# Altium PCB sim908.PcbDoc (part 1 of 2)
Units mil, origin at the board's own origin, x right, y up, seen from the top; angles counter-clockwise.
Board outline 6000 x 4000 mil, 2 copper layers (Top Layer, Bottom Layer); 77 components, 69 nets, 376 pads, 43 vias.
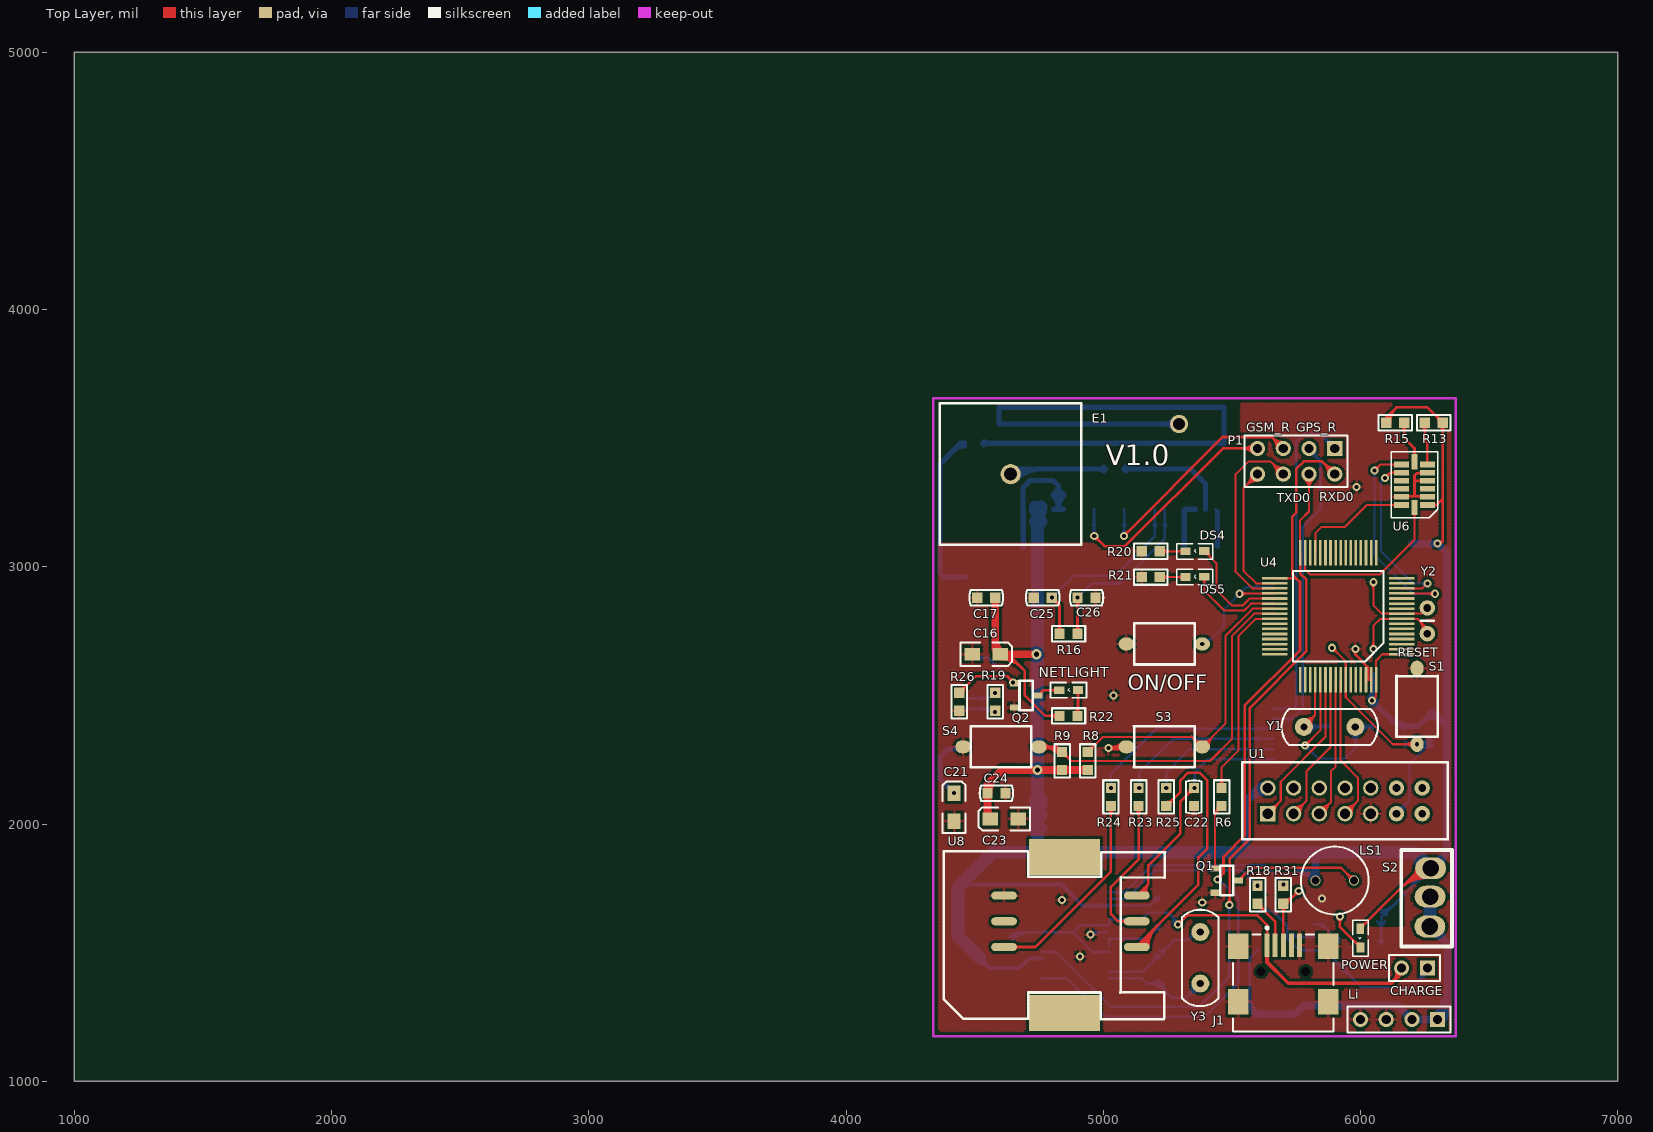
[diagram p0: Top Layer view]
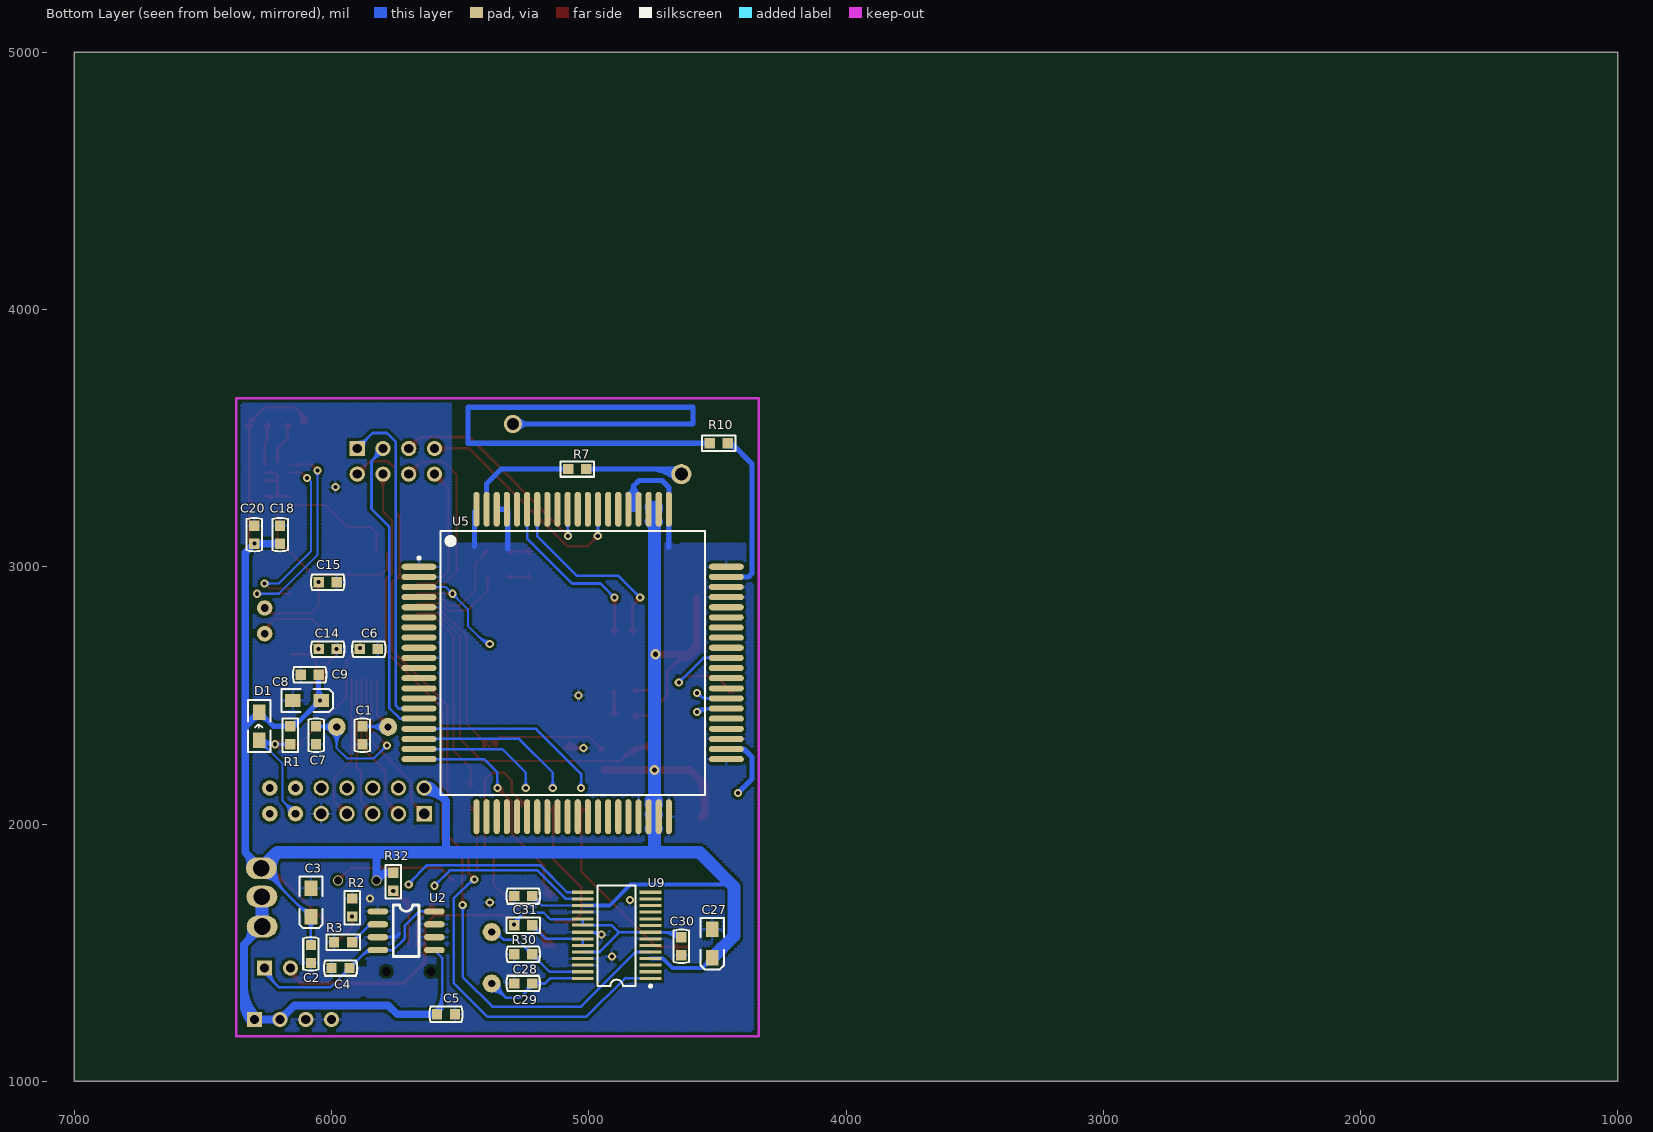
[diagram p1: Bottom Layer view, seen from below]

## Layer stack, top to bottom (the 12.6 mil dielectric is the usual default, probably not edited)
Top Layer: signal copper 1.4
Dielectric: dielectric 12.6, FR-4, Dk 4.8
Bottom Layer: signal copper 1.4

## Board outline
1000,1000 7000,1000 7000,5000 1000,5000

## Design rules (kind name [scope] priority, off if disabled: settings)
Clearance [All] p1: gap=10
HoleToHoleClearance [All] p1: gap=0 allowstackedmicrovias=TRUE
MinimumSolderMaskSliver [All] p1: minsoldermaskwidth=0
PolygonConnect [All] p1: connectstyle=Relief reliefconductorwidth=10 reliefentries=4 polygonreliefangle="90 Angle"
RoutingVias [All] p1: holewidth=28 width=50 viastyle="Through Hole" minholewidth=28 minwidth=50 maxholewidth=28 maxwidth=50
SilkToSilkClearance [All] p1: silktosilkclearance=0
SilkscreenOverComponentPads [All] p1: minsilkscreentomaskgap=0
SolderMaskExpansion [All] p1: expansion=4
TestPointUsage FabricationTestPointUsage [All] p1: valid=0 allowmultiple=FALSE
Testpoint FabricationTestpoint [All] p1: side=3 testpointundercomponent=TRUE minsize=40 maxsize=100 preferedsize=60 minholesize=0 maxholesize=40 preferedholesize=32 testpointgrid=1 style=297 order=0-112345678
Width [All] p1: maxlimit=100 minlimit=1 preferedwidth=10
20 further rules are at their usual default settings.

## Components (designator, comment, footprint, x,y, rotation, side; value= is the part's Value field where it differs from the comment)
C1 "Cap" C0603 5880,2310 r90 bottom
C2 "Cap" C0603 6080,1460 r90 bottom
C3 "Cap2" 3216C 6080,1640 r270 bottom
C4 "Cap" C0603 6000,1440 r180 bottom
C5 "Cap" C0603 5520,1260 r0 bottom
C6 "104" C0603 5820,2680 r0 bottom
C7 "Cap" C0603 6060,2310 r90 bottom
C8 "Cap2" 3216C 6040,2480 r180 bottom
C9 "Cap" C0603 6120,2580 r180 bottom
C14 "Cap" C0603 5980,2680 r0 bottom
C15 "Cap" C0603 5980,2940 r0 bottom
C16 "Cap2" 3216C 4600,2660 r0 top
C17 "Cap" C0603 4580,2880 r180 top
C18 "Cap" C0603 6200,3090 r90 bottom
C20 "Cap" C0603 6300,3160 r270 bottom
C21 "Cap2" 3216C 4420,2120 r90 top
C22 "Cap" C0603 5352.5,2070 r90 top
C23 "Cap2" 3216C 4560,2020 r180 top
C24 "Cap" C0603 4620,2120 r180 top
C25 "Cap" C0603 4800,2880 r180 top
C26 "Cap" C0603 4900,2880 r0 top
C27 "Cap2" 3216C 4520,1480 r270 bottom
C28 "Cap" C0603 5220,1493.33 r0 bottom
C29 "Cap" C0603 5220,1380 r0 bottom
C30 "Cap" C0603 4640,1560 r270 bottom
C31 "Cap" C0603 5220,1720 r0 bottom
CHARGE "充电" HDR1X2 6260,1440 r180 top (schematic designator Li)
D1 "1N4148" 1N5819 6280,2265.94 r270 bottom (schematic designator D401-1)
DS4 "LED" LED0603_AB 5360,3060 r180 top
DS5 "LED" LED0603_AB 5360,2960 r180 top
E1 "Antenna" GPS天线 4640,3360 r0 top
J1 "USB TYPE B" USB-Small 5700,1220 r270 top
Li "Comment" HDR1X4 6300,1240 r180 top
LS1 "Speaker" "BUZZER 7.6mm" 5900,1780 r0 top
NETLIGHT "LED" LED0603_AB 4869,2520 r180 top (schematic designator DS6)
ON/OFF "SW-PB" SWPB2-SMD 5080,2700 r0 top (schematic designator S5)
P1 "Header 4X2" HDR2X4 5900,3460 r180 top
POWER "LED" LED0603_AB 6000,1560 r270 top (schematic designator DS1)
Q1 "8050" NPN 5480,1780 r270 top
Q2 "" NPN 4700,2500 r270 top
R1 "Res2" R0603 6160,2310 r90 bottom
R2 "Res2" R0603 5920,1640 r90 bottom
R3 "Res2" R0603 5920,1540 r0 bottom
R6 "Res2" R0603 5460,2070 r90 top
R7 "Res2" R0603 5080,3380 r180 bottom
R8 "Res2" R0603 4940,2280 r270 top
R9 "Res2" R0603 4840,2280 r270 top
R10 "Res2" R0603 4460,3480 r0 bottom
R13 "Res2" R0603 6320,3560 r180 top
R15 "Res2" R0603 6100,3560 r0 top
R16 "Res2" R0603 4900,2740 r180 top
R18 "Res2" R0603 5600,1760 r270 top
R19 "Res2" R0603 4580,2440 r90 top
R20 "Res2" R0603 5220,3060 r180 top
R21 "Res2" R0603 5220,2960 r180 top
R22 "Res2" R0603 4900,2420 r180 top
R23 "Res2" R0603 5137.5,2140 r270 top
R24 "Res2" R0603 5030,2070 r90 top
R25 "Res2" R0603 5245,2140 r270 top
R26 "Res2" R0603 4440,2440 r90 top
R30 "Res2" R0603 5290,1606.67 r180 bottom
R31 "Res2" R0603 5700,1760 r270 top
R32 "Res2" R0603 5760,1740 r90 bottom
S1 "SW-PB" SWPB2-SMD 6220,2300 r90 top
S2 "5V" 小拨档开关 6260,1760 r90 top
S3 "SW-PB" SWPB2-SMD 5395,2300 r180 top
S4 "SW-PB" SWPB2-SMD 4760,2300 r180 top
U1 "MSP-JTAG" DIP14 5640,2040 r90 top
U2 "CN3052" SO-8 5820,1660 r180 bottom
U4 "MSP430F1612IPM" PM 6160,2660 r180 top
U5 "sim908" SIM908 5660,3000 r180 bottom
U6 "ADXL345" ADXL345_1 6260,3240 r180 top
U8 "SIM_CARD" SIM卡座 4380,1240 r0 top
U9 "PL2303" ssop28 4760,1400 r0 bottom
Y1 "8M" XTAL-0.2 5900,2220 r180 top
Y2 "32.768K" OSC1 6260,2840 r270 top
Y3 "12M" XTAL-0.2 5220,1460 r90 top

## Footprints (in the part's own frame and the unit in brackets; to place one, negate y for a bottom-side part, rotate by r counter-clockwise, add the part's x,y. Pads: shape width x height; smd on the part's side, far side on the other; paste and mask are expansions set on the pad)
1N5819 [mil]
  rect 60x50 smd: A(-60,-1) K(-169,-1)
  silkscreen extent -216,-44 -14,42
3216C [mil]
  rect 60x50 smd: 1(0,0) 2(-110,0)
  silkscreen extent -155,-45 45,45
ADXL345_1 [mm]
  rect 1.5x0.55 smd: 1(0,0) 2(0,-0.813) 3(0,-1.6) 4(0,-2.4) 5(0,-3.2) 6(0,-4) 8(2.553,-4) 9(2.553,-3.2) 10(2.553,-2.4) 11(2.553,-1.6) 12(2.553,-0.8) 13(2.553,0)
  rect 0.55x1.5 smd: 7(1.27,-4.267) 14(1.27,0.254)
  silkscreen extent -1.04,-5.26 3.57,1.26
"BUZZER 7.6mm" [mm]
  round 1 hole 0.762: 1(-1.9,0) 2(1.9,0)
  silkscreen extent -3.35,-3.35 3.35,3.35
C0603 [mil]
  rect 40x40 smd: 1(0,0) 2(70,0)
  silkscreen extent -30,-30 100,30
DIP14 [mil]
  rect 60x60 hole 40: 1(0,0)
  round 60 hole 40: 2(100,0) 3(0,-100) 4(100,-100) 5(0,-200) 6(100,-200) 7(0,-300) 8(100,-300) 9(0,-400) 10(100,-400)
  round 60 hole 30: 11(0,-500) 12(100,-500) 13(0,-600) 14(100,-600)
  silkscreen extent -100,-700 200,100
GPS天线 [mm]
  round 2 hole 1.3: 1(0,0)
  silkscreen extent -6.98,-6.98 6.98,6.98
HDR1X2 [mm] "Connector; Header; 2 Position"
  rect 1.5x1.5 hole 0.9: 1(0,0)
  round 1.5 hole 0.9: 2(2.54,0)
  silkscreen extent -1.27,-1.27 3.81,1.27
HDR1X4 [mm] "Connector; Header; 4 Position"
  rect 1.5x1.5 hole 0.9: 1(0,0)
  round 1.5 hole 0.9: 2(2.54,0) 3(5.08,0) 4(7.62,0)
  silkscreen extent -1.27,-1.27 8.89,1.27
HDR2X4 [mm] "Connector; Header; 4x2 Position"
  rect 1.5x1.5 hole 0.9: 1(0,0)
  round 1.5 hole 0.9: 2(0,2.54) 3(2.54,0) 4(2.54,2.54) 5(5.08,0) 6(5.08,2.54) 7(7.62,0) 8(7.62,2.54)
  silkscreen extent -1.27,-1.27 8.89,3.81
LED0603_AB [mil]
  rect 40x30 smd: 1(-32.93,-1) 2(40,0)
  silkscreen extent -66,-30 74,30
NPN [mm]
  rect 0.6x0.9 smd: 1(-1.2,-1.15) 2(1.2,-1.15) 3(0,1.15)
  silkscreen extent -1.45,-0.65 1.45,0.65
OSC1 [mil]
  round 60 hole 30: 1(0,0) 2(100,0)
  silkscreen extent 50,-25 50,25
PM [mm]
  rect 2.54x0.254 smd: 1(0,0) 2(0,-0.5) 3(0,-1) 4(0,-1.5) 5(0,-2) 6(0,-2.5) 7(0,-3) 8(0,-3.5) 9(0,-4) 10(0,-4.5) 11(0,-5) 12(0,-5.5) 13(0,-6) 14(0,-6.5) 15(0,-7) 16(0,-7.5) 33(12.54,-7.5) 34(12.54,-7) 35(12.54,-6.5) 36(12.54,-6) 37(12.54,-5.5) 38(12.54,-5) 39(12.54,-4.5) 40(12.54,-4) 41(12.54,-3.5) 42(12.54,-3) 43(12.54,-2.5) 44(12.54,-2) 45(12.54,-1.5) 46(12.54,-1) 47(12.54,-0.5) 48(12.54,0)
  rect 0.254x2.54 smd: 17(2.52,-10.02) 18(3.02,-10.02) 19(3.52,-10.02) 20(4.02,-10.02) 21(4.52,-10.02) 22(5.02,-10.02) 23(5.52,-10.02) 24(6.02,-10.02) 25(6.52,-10.02) 26(7.02,-10.02) 27(7.52,-10.02) 28(8.02,-10.02) 29(8.52,-10.02) 30(9.02,-10.02) 31(9.52,-10.02) 32(10.02,-10.02) 49(10.02,2.52) 50(9.52,2.52) 51(9.02,2.52) 52(8.52,2.52) 53(8.02,2.52) 54(7.52,2.52) 55(7.02,2.52) 56(6.52,2.52) 57(6.02,2.52) 58(5.52,2.52) 59(5.02,2.52) 60(4.52,2.52) 61(4.02,2.52) 62(3.52,2.52) 63(3.02,2.52) 64(2.52,2.52)
  silkscreen extent 1.81,-8.21 10.73,0.71
R0603 [mil]
  rect 40x40 smd: 1(0,0) 2(70,0)
  silkscreen extent -30,-30 100,30
SIM908 [mm] "QFP, 80-Leads, Body 33.0x33.0mm (max), Pitch 1.00mm, IPC Medium Density"
  oval 3.45x0.6 smd: 1(0,0) 2(0,-1) 3(0,-2) 4(0,-3) 5(0,-4) 6(0,-5) 7(0,-6) 8(0,-7) 9(0,-8) 10(0,-9) 11(0,-10) 12(0,-11) 13(0,-12) 14(0,-13) 15(0,-14) 16(0,-15) 17(0,-16) 18(0,-17) 19(0,-18) 20(0,-19) 41(30.35,-19) 42(30.35,-18) 43(30.35,-17) 44(30.35,-16) 45(30.35,-15) 46(30.35,-14) 47(30.35,-13) 48(30.35,-12) 49(30.35,-11) 50(30.35,-10) 51(30.35,-9) 52(30.35,-8) 53(30.35,-7) 54(30.35,-6) 55(30.35,-5) 56(30.35,-4) 57(30.35,-3) 58(30.35,-2) 59(30.35,-1) 60(30.35,0)
  oval 0.6x3.45 smd: 21(5.675,-24.675) 22(6.675,-24.675) 23(7.675,-24.675) 24(8.675,-24.675) 25(9.675,-24.675) 26(10.675,-24.675) 27(11.675,-24.675) 28(12.675,-24.675) 29(13.675,-24.675) 30(14.675,-24.675) 31(15.675,-24.675) 32(16.675,-24.675) 33(17.675,-24.675) 34(18.675,-24.675) 35(19.675,-24.675) 36(20.675,-24.675) 37(21.675,-24.675) 38(22.675,-24.675) 39(23.675,-24.675) 40(24.675,-24.675) 61(24.675,5.675) 62(23.675,5.675) 63(22.675,5.675) 64(21.675,5.675) 65(20.675,5.675) 66(19.675,5.675) 67(18.675,5.675) 68(17.675,5.675) 69(16.675,5.675) 70(15.675,5.675) 71(14.675,5.675) 72(13.675,5.675) 73(12.675,5.675) 74(11.675,5.675) 75(10.675,5.675) 76(9.675,5.675) 77(8.675,5.675) 78(7.675,5.675) 79(6.675,5.675) 80(5.675,5.675)
  silkscreen extent -0.13,-22.55 28.23,3.55
SIM卡座 [mm]
  oval 2.54x0.8 smd: 1(19.062,12.237) 2(19.062,9.697) 3(19.062,7.157) 4(5.954,12.237) 5(5.954,9.697) 6(5.954,7.157)
  rect 7x3.556 smd: ""(11.939,0.626) ""(11.941,16.052)
  silkscreen extent -0.01,0.01 21.85,16.61
SO-8 [mil]
  oval 80x24 smd: 1(0,0) 2(0,-50) 3(0,-100) 4(0,-150) 5(220,-150) 6(220,-100) 7(220,-50) 8(220,0)
  silkscreen extent 60,-175 160,25
ssop28 [mm]
  rect 2.15x0.305 smd: 1(0,0) 2(0,-0.65) 3(0,-1.3) 4(0,-1.95) 5(0,-2.6) 6(0,-3.25) 7(0,-3.9) 8(0,-4.55) 9(0,-5.2) 10(0,-5.85) 11(0,-6.552) 12(0,-7.202) 13(0,-7.852) 14(0,-8.502) 15(6.7,-8.502) 16(6.7,-7.852) 17(6.7,-7.202) 18(6.7,-6.552) 19(6.7,-5.85) 20(6.7,-5.252) 21(6.7,-4.55) 22(6.7,-3.9) 23(6.7,-3.25) 24(6.7,-2.6) 25(6.7,-1.95) 26(6.7,-1.3) 27(6.7,-0.65) 28(6.7,0)
  silkscreen extent -0.12,-9.14 5.22,0.9
SWPB2-SMD [mil]
  oval 60x50 smd: 1(10,0) 2(305,0)
  silkscreen extent 40,-80 276,80
USB-Small [mm] "Connector; USB2.0, Type B, SM; 5 Position; Right Angle"
  rect 2.3x0.5 smd: 1(-7.85,-1.6) 2(-7.85,-0.8) 3(-7.85,0) 4(-7.85,0.8) 5(-7.85,1.6)
  rect 2.5x2 smd: 6(-7.75,4.45) 7(-2.25,4.45) 8(-7.75,-4.45) 9(-2.25,-4.45)
  round 0.6 hole 0.9 unplated: MH1(-5.25,2.2) MH2(-5.25,-2.2)
  silkscreen extent -9.67,-4.95 0.7,4.95, body extent -8.9,-4.95 0.7,4.95, height 3.9
XTAL-0.2 [mil]
  round 70 hole 28: 1(-79.92,-157.48) 2(120.08,-157.48)
  silkscreen extent -168,-228 207,-86
小拨档开关 [mil]
  oval 85x120 hole 65: 1(-158.46,-9.84) 2(-42.32,-10.83) 3(67.91,-12.8)
  silkscreen extent -236,-96 139,101

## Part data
C1 C2 C3 C4 C5 C7 C8 C9 C14 C15 C16 C17 C18 C20 C21 C22 C23 C24 C25 C26 C27 C28 C29 C30 C31: "Capacitor"
C6: library part Cap, "Capacitor"
CHARGE: library part "Header 2", "Header, 2-Pin"
D1: library part DIODE1, "Diode"
DS4 DS5 NETLIGHT POWER: library part LED3, "Typical BLUE SiC LED"
J1: library part miniUSB, "USB, SMD, Type B, Molex"
LS1: "Loudspeaker"
ON/OFF S1 S3 S4: "Switch"
P1: "Header, 4-Pin, Dual row"
Q1: library part QNPN, "NPN Bipolar Transistor"
Q2: library part IRF540
R1 R2 R3 R6 R7 R8 R9 R10 R13 R15 R16 R18 R19 R20 R21 R22 R23 R24 R25 R26 R30 R31 R32: "Resistor"
S2: library part CON3, "Connector"
U4: "MSP430F1611IPM"
Y1 Y2 Y3: library part XTAL, "Crystal Oscillator"

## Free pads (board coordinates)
  round 70.87 hole 47.24: 1(5295,3555)

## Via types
v1: diameter 31.5, hole 15.75, Top Layer to Bottom Layer, 41 vias
v2: diameter 39.37, hole 19.68, Top Layer to Bottom Layer, 2 vias

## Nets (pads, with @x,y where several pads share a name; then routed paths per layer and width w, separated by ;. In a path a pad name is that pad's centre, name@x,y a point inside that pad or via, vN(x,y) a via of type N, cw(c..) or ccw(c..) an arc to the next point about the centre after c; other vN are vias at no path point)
3.3V: C2.2 C3.1 C8.1 C9.2 C16.1 C17.1 C18.1 C20.2 C23.1 C24.2 C27.1 C31.1 D1.K LS1.1 POWER.1 R1.2 R8.2 R9.2 R13.1 R15.1 R22.2 R32.2 S2.3 U1.2 U4.1 U4.64 U5.38 U5.39 U5.62 U5.63 U6.1 U9.4 U9.17 | length 13212.1
  Top Layer w8: v1(6045,2480) 6060.79,2495.79 U4.64@6060.79,2560.79 6060.79,2635.79 6085,2660 U4.1@6160,2660
  Top Layer w10: C16.1@4600,2660 4630,2660 4695,2595 4695,2499.54 4774.54,2420 R22.2@4830,2420 ; C16.1@4605,2640 cw(c4605,2531.36) 4681.82,2608.18 ; C16.1@4605,2650 cw(c4605,2565.5) 4664.75,2625.25 ; C16.1@4605,2660 cw(c4605,2599.64) 4647.68,2642.32 ; C16.1@4605,2670 cw(c4605,2633.79) 4630.61,2659.39 ; R22.2@4819.39,2409.39 ccw(c4793.79,2383.79) 4793.79,2420 ccw(c4793.79,2456.21) R22.2@4819.39,2430.61 ; POWER.1@5999,1592.93 6233.98,1827.91 S2.3@6272.8,1827.91 ; POWER.1@5999,1607.93 ccw(c5999,1644.14) 6024.61,1618.53 ; POWER.1@6009,1597.93 cw(c6021.07,1597.93) POWER.1@6012.54,1606.46 ; R15.1@6095,3560 cw(c6131.21,3560) 6105.61,3585.61 ; R15.1@6100,3560 6100,3580 6140,3620 6260,3620 R13.1@6320,3560 6320,3265 ; R15.1@6105,3560 cw(c6165.36,3560) 6122.68,3602.68 ; R15.1@6115,3560 cw(c6199.5,3560) 6139.75,3619.75 ; 6154.9,1748.83 cw(c6255.3,1648.43) S2.3@6255.3,1790.41 ; 6171.97,1765.9 cw(c6255.3,1682.58) S2.3@6255.3,1800.41 ; 6189.04,1782.97 cw(c6255.3,1716.72) S2.3@6255.3,1810.41 ; 6206.11,1800.04 cw(c6255.3,1750.86) S2.3@6255.3,1820.41 ; 6206.35,1800.27 ccw(c6178.71,1827.91) S2.3@6217.8,1827.91 ; U6.1@6260,3240 6295,3240 6320,3265 ; U6.1@6282.82,3235.88 cw(c6292.77,3225.93) 6292.77,3240 cw(c6292.77,3254.07) U6.1@6282.82,3244.12 ; v1@6305,3085 6320,3100 ; R13.1@6305,3560 ccw(c6268.79,3560) 6294.39,3585.61 ccw(c6320,3611.21) R13.1@6320,3575 ; v1@6306.17,3098.8 ccw(c6312.37,3107.63) 6320,3100 ; R13.1@6309.39,3549.39 cw(c6283.79,3523.79) 6320,3523.79 cw(c6356.21,3523.79) R13.1@6330.61,3549.39 ; 6320,3100 6320,3265
  Top Layer w30: C23.1@4550,2030 C24.2@4550,2120 4550,2155 4605,2210 v2(4745,2210) R9.2@4840,2210 R8.2@4940,2210 ; 4550,2056.21 ccw(c4591.21,2056.21) C23.1@4562.07,2027.07 ; C24.2@4555,2120 cw(c4651.57,2120) 4583.28,2188.28 ; 4580,2720.36 ccw(c4655.36,2720.36) C16.1@4602.07,2667.07 ; C17.1@4580,2880 4580,2680 C16.1@4600,2660 ; 4630,2660 v2(4740,2660)
  Bottom Layer w8: U9.17@5023.78,1683.54 5183.54,1683.54 C31.1@5220,1720 ; C31.1@5204,1720 cw(c5165.37,1720) 5192.69,1692.69 cw(c5220,1665.37) C31.1@5220,1704
  Bottom Layer w10: C3.1@6065.86,1620.86 cw(c6031.72,1586.72) 6080,1586.72 cw(c6128.28,1586.72) C3.1@6094.14,1620.86 ; C2.2@6071,1542 ccw(c6057.5,1560) 6080,1560 ; C2.2@6080,1530 6080,1560 ; C3.1@6080,1655 ccw(c6080,1703) 6113.94,1669.06 ; C3.1@6080,1665 ccw(c6080,1737.14) 6131.01,1686.13 ; C2.2@6089,1542 cw(c6102.5,1560) 6080,1560 ; C3.1@6100,1645 cw(c6124.43,1645) 6107.15,1662.27 ; 6178.9,1734.02 ccw(c6085.01,1827.91) S2.3@6217.8,1827.91 ; 6195.98,1751.09 ccw(c6119.16,1827.91) S2.3@6227.8,1827.91 ; 6213.05,1768.16 ccw(c6153.3,1827.91) S2.3@6237.8,1827.91 ; 6221.15,1776.27 cw(c6255.3,1742.13) S2.3@6255.3,1790.41 ; 6230.12,1785.24 ccw(c6187.44,1827.91) S2.3@6247.8,1827.91 ; S2.3@6272.8,1827.91 6084.88,1640 C3.1@6080,1640 6080,1560
  Bottom Layer w15: 4460,1765 4837.09,1765 4918.54,1683.54 U9.17@5023.78,1683.54 ; C27.1@4520,1457.5 cw(c4520,1403.18) 4558.41,1441.59 ; C27.1@4520,1480 4560,1440 4675,1440 4711.77,1476.77 U9.4@4760,1476.77 ; C27.1@4537.5,1475 ccw(c4567.68,1475) 4546.34,1453.66 ; 4705.91,1470.91 cw(c4723.68,1453.15) 4723.68,1478.27 ccw(c4723.68,1453.15) 4705.91,1470.91
  Bottom Layer w20: C8.1@6034.39,2490.61 ccw(c5996.72,2528.28) 6050,2528.28 ; C8.1@6040,2480 6050,2490 C9.2@6050,2580 ; C8.1@6040.94,2484.06 ccw(c6019.05,2505.95) 6050,2505.95 ; C9.2@6042.93,2572.93 cw(c6025.86,2555.86) 6050,2555.86 cw(c6074.14,2555.86) C9.2@6057.07,2572.93 ; C8.1@6045,2465 cw(c6045,2428.79) 6070.61,2454.39 cw(c6096.21,2480) C8.1@6060,2480 ; v1(6045,2480) 6145,2380 R1.2@6160,2380 6226.06,2380 D1.K@6281,2434.94 ; 6117.32,2407.68 ccw(c6160,2450.36) R1.2@6160,2390 ; R1.2@6167.07,2372.93 cw(c6184.14,2355.86) 6184.14,2380 cw(c6184.14,2404.14) R1.2@6167.07,2387.07 ; 6246.86,2400.79 cw(c6281,2366.65) D1.K@6281,2414.94 ; D1.K@6258.93,2412.87 ccw(c6241.86,2429.94) D1.K@6266,2429.94
  Bottom Layer w30: U5.62@4725.95,3220.91 ccw(c4745.2,3245.51) U5.63@4767.28,3223.43 ; U5.39@4727.91,2028.54 4745,2028.54 U5.38@4767.28,2028.54 ; U5.62@4727.91,3223.43 U5.63@4767.28,3223.43 4754.43,3210.57 ; 5554.64,2089.64 cw(c5640,2004.29) U1.2@5640,2125 ; 5555,1890 5555,2090 5605,2140 ; 5587.5,2122.5 cw(c5612.74,2097.26) U1.2@5631.93,2127.35 ; 5605.86,2140.86 cw(c5640,2106.71) U1.2@5640,2155 ; U1.2@5629.14,2129.66 ccw(c5605,2106.67) 5605,2140 ; U1.2@5629.14,2150.34 cw(c5605,2173.33) 5605,2140 ; U1.2@5640,2140 5605,2140 ; R32.2@5760,1810 5795.2,1810 LS1.1@5825.2,1780 5825.2,1889.8 ; C18.1@6200,3090 v1(6300,3090) 6335,3055 6335,2380.94 ; S2.3@6272.8,1827.91 6335,1890.12 ; D1.K@6281,2419.94 cw(c6281,2383.72) 6306.61,2409.33 ; D1.K@6281,2434.94 6335,2380.94 ; S2.3@6317.32,1832.98 cw(c6380.32,1844.8) 6335,1890.12 ; 6335,1890.12 6335,2380.94
  Bottom Layer w50: C27.1@4520,1480 4435,1565 4435,1755 4570,1890 4745,1890 ; U5.39@4737.24,1981.77 cw(c4718.5,1963.03) 4745,1963.03 ; U5.39@4737.24,2037.87 cw(c4718.5,2019.13) 4745,2019.13 ; U5.39@4737.24,2075.32 ccw(c4718.5,2094.06) 4745,2094.06 ; 4737.24,2093.97 cw(c4718.5,2075.24) 4745,2075.24 ; U5.62@4737.24,3176.65 cw(c4718.5,3157.91) 4745,3157.91 ; U5.62@4737.24,3232.75 cw(c4718.5,3214.02) 4745,3214.02 ; 4745,1950.48 cw(c4789.24,1950.48) U5.38@4757.96,1981.77 ; 4745,2006.59 cw(c4789.24,2006.59) U5.38@4757.96,2037.87 ; 4745,2062.69 cw(c4789.24,2062.69) 4757.96,2093.97 ; 4745,2106.6 ccw(c4789.24,2106.6) U5.38@4757.96,2075.32 ; 4745,3145.37 cw(c4789.24,3145.37) U5.63@4757.96,3176.65 ; 4745,3201.47 cw(c4789.24,3201.47) U5.63@4757.96,3232.75 ; 4754.43,3210.57 4745,3201.14 v2(4745,2210) 4745,2028.54 4745,1890 ; 6147.91,1890 6120,1890 ; 6213.05,1887.66 cw(c6153.3,1827.91) S2.3@6237.8,1827.91 ; S2.3@6272.8,1827.91 6210.71,1890 6120,1890 ; 4745,1890 5555,1890 6120,1890
5V: C30.1 CHARGE.2 J1.1 R30.1 U9.8 U9.19 U9.20 U9.24 | length 2468.5
  Top Layer w10: v1(5290,1610) 5325,1645 5600,1645 5637.01,1607.99 J1.1@5637.01,1529.06 ; v1@5290,1620.75 ccw(c5290,1646.7) 5308.35,1628.35 ccw(c5326.7,1610) v1@5300.75,1610 ; J1.1@5633.58,1567.91 ccw(c5625.32,1576.18) 5637.01,1576.18 ccw(c5648.7,1576.18) J1.1@5640.43,1567.91
  Top Layer w15: J1.1@5637.01,1529.06 5637.01,1462.99 5719.02,1380.98 6120.98,1380.98 CHARGE.2@6160,1420 ; 6130.99,1390.99 ccw(c6104.02,1417.95) CHARGE.2@6139.5,1431.93 ; 6147.17,1407.17 ccw(c6127.23,1427.1) CHARGE.2@6153.46,1437.43
  Bottom Layer w10: C30.1@4636.46,1563.54 cw(c4674.12,1525.88) 4674.12,1579.13 ; C30.1@4640,1560 4659.13,1579.13 U9.8@4760,1579.13 4760.87,1580 4880,1580 ; C30.1@4643.54,1556.46 cw(c4698.26,1501.74) 4698.26,1579.13 ; C30.1@4650.61,1549.39 cw(c4722.41,1477.59) U9.8@4722.41,1579.13 ; U9.24@5023.78,1502.36 4957.64,1502.36 4880,1580 ; 5254.97,1655.03 cw(c5206.6,1606.67) R30.1@5275,1606.67 ; 5264.58,1645.42 cw(c5229.16,1610) R30.1@5279.25,1610 ; 5272.04,1637.96 cw(c5240.74,1606.67) R30.1@5285,1606.67 ; 5281.65,1628.35 cw(c5263.3,1610) R30.1@5289.25,1610 ; R30.1@5290,1606.67 5290,1620 5255,1655 5175,1655 5150.31,1630.31 U9.19@5023.78,1630.31 U9.20@5023.78,1606.77 4911.77,1606.77 4885,1580 4880,1580
5V_LI: C4.2 CHARGE.1 U2.4 U2.8 | length 1234.2
  Top Layer w10: CHARGE.1@6260,1420 CHARGE.1@6260,1440
  Bottom Layer w10: U2.8@5600,1660 5660,1660 5715,1605 5715,1555 5760,1510 U2.4@5820,1510 5860,1510 C4.2@5930,1440 6005,1365 6205,1365 CHARGE.1@6260,1420 ; U2.8@5632.95,1655.05 cw(c5644.9,1643.1) 5644.9,1660 cw(c5644.9,1676.9) U2.8@5632.95,1664.95 ; U2.4@5787.05,1505.05 ccw(c5775.1,1493.1) 5775.1,1510 ccw(c5775.1,1526.9) U2.4@5787.05,1514.95 ; U2.4@5848,1503 cw(c5848,1457.13) 5880.44,1489.56 ; U2.4@5848,1513 cw(c5848,1491.27) 5863.36,1506.64 ; C4.2@5915,1440 ccw(c5878.79,1440) 5904.39,1465.61 ccw(c5930,1491.21) C4.2@5930,1455 ; C4.2@5930,1425 cw(c5930,1388.79) 5955.61,1414.39 cw(c5981.21,1440) C4.2@5945,1440 ; 6215,1375 ccw(c6163.36,1426.64) CHARGE.1@6235.7,1436.64 ; 6229.22,1389.22 ccw(c6188.35,1430.1) CHARGE.1@6245.61,1438.01 ; 6243.45,1403.45 ccw(c6213.34,1433.55) CHARGE.1@6255.52,1439.38
D+: R31.1 U9.15 | length 789.1
  Bottom Layer w10: U9.15@5023.78,1734.72 5084.72,1734.72 5190,1840 5230,1840 5628.28,1840 v1@5699.14,1769.14 ; 5679.33,1788.95 cw(c5655.38,1765) v1@5689.25,1765 ; 5687.26,1781.03 ccw(c5700,1793.77) v1@5700,1775.75
  other v1: 5700,1765
D-: R18.1 U9.16 | length 687.8
  Bottom Layer w10: U9.16@5023.78,1709.13 5089.13,1709.13 5200,1820 5540,1820 v1(5600,1760) ; v1@5589.25,1760 ccw(c5563.3,1760) 5581.65,1778.35 ccw(c5600,1796.7) v1@5600,1770.75
GND: C1.1 C2.1 C3.2 C4.1 C5.1 C6.1 C7.1 C8.2 C9.1 C14.1 C15.1 C16.2 C17.2 C18.2 C20.1 C21.2 C22.1 C23.2 C24.1 C25.2 C26.2 C27.2 C28.2 C29.2 C30.2 C31.2 J1.5 J1.6 J1.7 J1.8 J1.9 Li.3 Li.4 ON/OFF.1 Q1.2 Q2.2 R2.2 R3.2 R20.2 R21.2 R26.1 S1.2 S3.2 S4.2 U1.9 U2.1 U2.3 U2.6 U2.7 U4.62 U4.63 U5.1 U5.2 U5.5 U5.10 U5.14 U5.37 U5.40 U5.41 U5.43 U5.57 U5.58 U5.60 U5.61 U5.64 U5.65 U5.77 U5.78 U5.80 U6.2 U6.4 U6.5 U6.12 U8.4 U9.7 U9.18 U9.21 U9.25 U9.26 | length 2029.6
  Top Layer w10: v1@5973.63,2671.35 cw(c5964.34,2658.73) 5980,2658.73 ; v1(5980,2680) 5980,2658.73 ; v1@5986.37,2671.35 ccw(c5995.66,2658.73) 5980,2658.73 ; U4.62@6021.42,2560.79 6030,2560.79 ; U4.63@6041.1,2560.79 6030,2560.79 ; U6.12@6159.5,3271.5 6162.53,3274.53 6257.47,3274.53 U6.2@6254.83,3277.17 ; 6212.83,3277.17 6210,3280 6210,3325 ; 6221.13,3274.53 cw(c6221.13,3251.83) U6.2@6237.18,3267.88 ; 6221.13,3363.47 ccw(c6221.13,3386.17) U6.5@6237.18,3370.12 ; 6226.03,3335 cw(c6226.03,3319.23) U6.4@6237.18,3330.38 ; 6228.44,3335 ccw(c6228.44,3347.36) U6.4@6237.18,3338.62 ; U6.4@6260,3334.5 6259.5,3335 6220,3335 6210,3325 ; U6.5@6260,3366 6257.47,3363.47 6218.47,3363.47 6210,3355 6210,3325 ; 5980,2658.73 6030,2608.73 6030,2560.79
  Top Layer w20: v1(5020,2295) 5085,2295 S3.2@5090,2300 ; 5036.72,2295 ccw(c5036.72,2348.28) S3.2@5074.39,2310.61
  Bottom Layer w10: v1(4950,1570) 4959.13,1579.13 U9.21@5013.78,1579.13 ; v1@4950.53,1569.47 cw(c4973.86,1546.14) 4973.86,1579.13 ; v1@4957.6,1562.4 cw(c4998,1522) U9.21@4998,1579.13
  Bottom Layer w11.81: U5.61@4688.54,3223.43 U5.61@4688.97,3223 ; U5.77@5314.95,3219.91 U5.77@5318.46,3223.43 ; U5.80@5436.57,3223.43 U5.80@5444.87,3215.13 ; 5735.91,1575 5750.91,1560 U2.3@5820,1560
  Bottom Layer w20: U5.61@4688.54,3223.43 4688.54,3308.54 4715,3335 4805,3335 4825,3315 ; 4688.97,3075 U5.61@4688.97,3223 ; U5.64@4805.37,3278.25 cw(c4757.99,3230.86) 4825,3230.86 ; U5.64@4805.73,3281.08 ccw(c4785.52,3315) 4825,3315 ; U5.64@4806.65,3223.43 4825,3223.43 ; U5.64@4815.96,3263.9 ccw(c4806.49,3279.8) 4825,3279.8 ; 4819.52,3292.39 cw(c4806.27,3279.15) 4825,3279.15 ; 4825,3224.4 cw(c4901.15,3224.4) U5.65@4847.3,3278.25 ; 4825,3252.86 ccw(c4833.9,3252.86) 4830.21,3244.77 ; 4825,3272.68 cw(c4852.87,3272.68) 4833.16,3292.39 ; 4825,3283.93 ccw(c4848.03,3283.93) U5.65@4838.49,3262.97 ; U5.65@4846.02,3223.43 4825,3223.43 ; U5.65@4846.77,3281.18 cw(c4862.16,3315) 4825,3315 ; 5314.95,3070 U5.77@5314.95,3219.91 ; U5.77@5318.46,3223.43 U5.78@5357.83,3223.43 ; 5444.87,3080 U5.80@5444.87,3215.13 ; 4825,3223.43 4825,3315
  other v1: 4910,1485 5385,1695 4840,1705 5850,1710 5040,2500 5985,3310
GPS_RXD: P1.3 U5.16 | length 1335.8
  Bottom Layer w10: U5.16@5660,2409.45 5734.45,2409.45 5775,2450 5775,3155 5844.53,3224.53 5844.53,3410.47 5800,3455 P1.3@5800,3460 ; U5.16@5720.92,2404.63 cw(c5732.55,2393.01) 5732.55,2409.45 cw(c5732.55,2425.89) U5.16@5720.92,2414.27 ; P1.3@5800,3435.47 cw(c5800,3388.33) 5833.34,3421.66 ; P1.3@5814.51,3459.23 ccw(c5854.43,3457.11) 5826.16,3428.84 ; P1.3@5824.49,3458.7 ccw(c5884.56,3455.51) 5842.03,3412.97
GPS_TXD: P1.1 U5.15 | length 1482.9
  Bottom Layer w10: U5.15@5660,2448.82 5738.82,2448.82 5750,2460 5750,3485 5785,3520 5840,3520 P1.1@5900,3460 ; U5.15@5720.92,2444 cw(c5732.55,2432.38) 5732.55,2448.82 cw(c5732.55,2465.26) U5.15@5720.92,2453.64 ; P1.1@5875.47,3460 ccw(c5816.26,3460) 5858.13,3501.87 ccw(c5900,3543.74) P1.1@5900,3484.53 ; P1.1@5885.47,3460 ccw(c5850.4,3460) 5875.2,3484.8 ccw(c5900,3509.6) P1.1@5900,3474.53
GSM_RXD: P1.7 U5.68 | length 1167.8
  Top Layer w10: v1@4965,3109.25 cw(c4965,3083.3) 4983.35,3101.65 cw(c5001.7,3120) v1@4975.75,3120 ; v1(4965,3120) 5005,3080 5085,3080 5465,3460 P1.7@5600,3460 ; P1.7@5582.66,3442.66 ccw(c5540.79,3400.79) 5540.79,3460 ccw(c5540.79,3519.21) P1.7@5582.66,3477.34 ; P1.7@5589.73,3449.73 ccw(c5564.93,3424.93) 5564.93,3460 ccw(c5564.93,3495.07) P1.7@5589.73,3470.27
  Bottom Layer w10: v1@4957.4,3127.6 ccw(c4941.14,3143.86) 4964.13,3143.86 ; U5.68@4959.32,3162.51 cw(c4947.69,3150.88) 4964.13,3150.88 cw(c4980.58,3150.88) U5.68@4968.95,3162.51 ; v1@4964.13,3120 U5.68@4964.13,3223.43 ; 4964.13,3148.04 ccw(c4993.04,3148.04) v1@4972.6,3127.6
GSM_TXD: P1.5 U5.71 | length 1159.4
  Top Layer w10: v1(5080,3120) 5464.53,3504.53 5655.47,3504.53 P1.5@5700,3460 ; v1@5080,3130.75 ccw(c5080,3156.7) 5098.35,3138.35 ccw(c5116.7,3120) v1@5090.75,3120 ; P1.5@5675.47,3460 ccw(c5616.26,3460) 5658.13,3501.87 ccw(c5700,3543.74) P1.5@5700,3484.53 ; P1.5@5685.47,3460 ccw(c5650.4,3460) 5675.2,3484.8 ccw(c5700,3509.6) P1.5@5700,3474.53
  Bottom Layer w10: v1@5072.4,3127.6 ccw(c5048.63,3151.37) 5082.24,3151.37 ; U5.71@5077.43,3162.51 cw(c5065.8,3150.88) 5082.24,3150.88 cw(c5098.69,3150.88) U5.71@5087.06,3162.51 ; v1@5082.24,3117.24 U5.71@5082.24,3223.43 ; 5082.24,3140.53 ccw(c5100.53,3140.53) v1@5087.6,3127.6
INT1: U4.13 U6.8 | length 1075.2
  Top Layer w8: v1(6055,3375) 6077.5,3397.5 U6.8@6159.5,3397.5 ; v1@6055,3386.75 ccw(c6055,3415.11) 6075.06,3395.06 ccw(c6095.11,3375) v1@6066.75,3375 ; U6.8@6135.97,3392.67 ccw(c6124.32,3381.02) 6124.32,3397.5 ccw(c6124.32,3413.98) U6.8@6135.97,3402.33 ; U4.13@6160,2896.22 6285,2896.22 v1(6290,2895) ; 6258.69,2896.22 cw(c6258.69,2863.69) v1@6281.69,2886.69 ; 6264.58,2896.22 ccw(c6264.58,2920.42) v1@6281.69,2903.31
  Bottom Layer w8: v1@6046.69,3366.69 cw(c6026.64,3346.64) 6055,3346.64 cw(c6083.36,3346.64) v1@6063.31,3366.69 ; v1(6055,3375) 6055,3045 6205,2895 v1(6290,2895) ; v1@6281.69,2886.69 ccw(c6261.64,2866.64) 6261.64,2895 ccw(c6261.64,2923.36) v1@6281.69,2903.31
INT2: U4.14 U6.9 | length 819.1
  Top Layer w8: v1(6095,3345) 6116,3366 U6.9@6159.5,3366 ; v1@6095,3356.75 ccw(c6095,3385.11) 6115.06,3365.06 ccw(c6135.11,3345) v1@6106.75,3345 ; U6.9@6135.97,3361.17 ccw(c6124.32,3349.52) 6124.32,3366 ccw(c6124.32,3382.48) U6.9@6135.97,3370.83 ; U4.14@6160,2915.91 6240.9,2915.91 v1(6260,2935)
  Bottom Layer w8: v1(6095,3345) 6080,3330 6080,3060 6205,2935 v1(6260,2935) ; v1@6251.69,2926.69 ccw(c6231.64,2906.64) 6231.64,2935 ccw(c6231.64,2963.36) v1@6251.69,2943.31
NetC1_2: C1.2 U4.52 Y1.2 | length 762.1
  Top Layer w8: Y1.2@5779.92,2377.48 5779.92,2379.92 5823.88,2423.88 ; Y1.2@5781.62,2400.42 ccw(c5784.45,2438.62) 5811.53,2411.53 ; Y1.2@5782.21,2408.4 ccw(c5786.15,2461.61) 5823.88,2423.88 ; Y1.2@5802.62,2381.17 cw(c5838.64,2387.04) 5812.84,2412.84 ; Y1.2@5810.52,2382.46 cw(c5857.63,2390.13) 5823.88,2423.88 ; U4.52@5824.57,2560.79 5823.88,2560.1 5823.88,2423.88
  Bottom Layer w8: Y1.2@5779.92,2377.48 5782.44,2380 C1.2@5880,2380 ; Y1.2@5790.53,2366.87 cw(c5822.22,2335.18) 5822.22,2380 ; Y1.2@5796.18,2361.22 cw(c5841.53,2315.87) 5841.53,2380 ; Y1.2@5796.18,2393.74 ccw(c5829.37,2426.92) 5829.37,2380 ; Y1.2@5801.84,2355.56 cw(c5860.85,2296.56) C1.2@5860.85,2380 ; Y1.2@5801.84,2399.4 ccw(c5848.68,2446.24) 5848.68,2380 ; C1.2@5868.69,2368.69 ccw(c5841.37,2341.37) 5841.37,2380 ccw(c5841.37,2418.63) C1.2@5868.69,2391.31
